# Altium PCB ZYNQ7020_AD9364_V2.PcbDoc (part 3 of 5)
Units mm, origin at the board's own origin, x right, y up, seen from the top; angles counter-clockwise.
Board outline 88.95 x 91.52 mm, 4 copper layers (Top Layer, Layer 1, Layer 2, Bottom Layer), stack 0.603 mm thick; 285 components, 278 nets, 1497 pads, 1247 vias.
Unrouted connection lines stored in the file: 367.
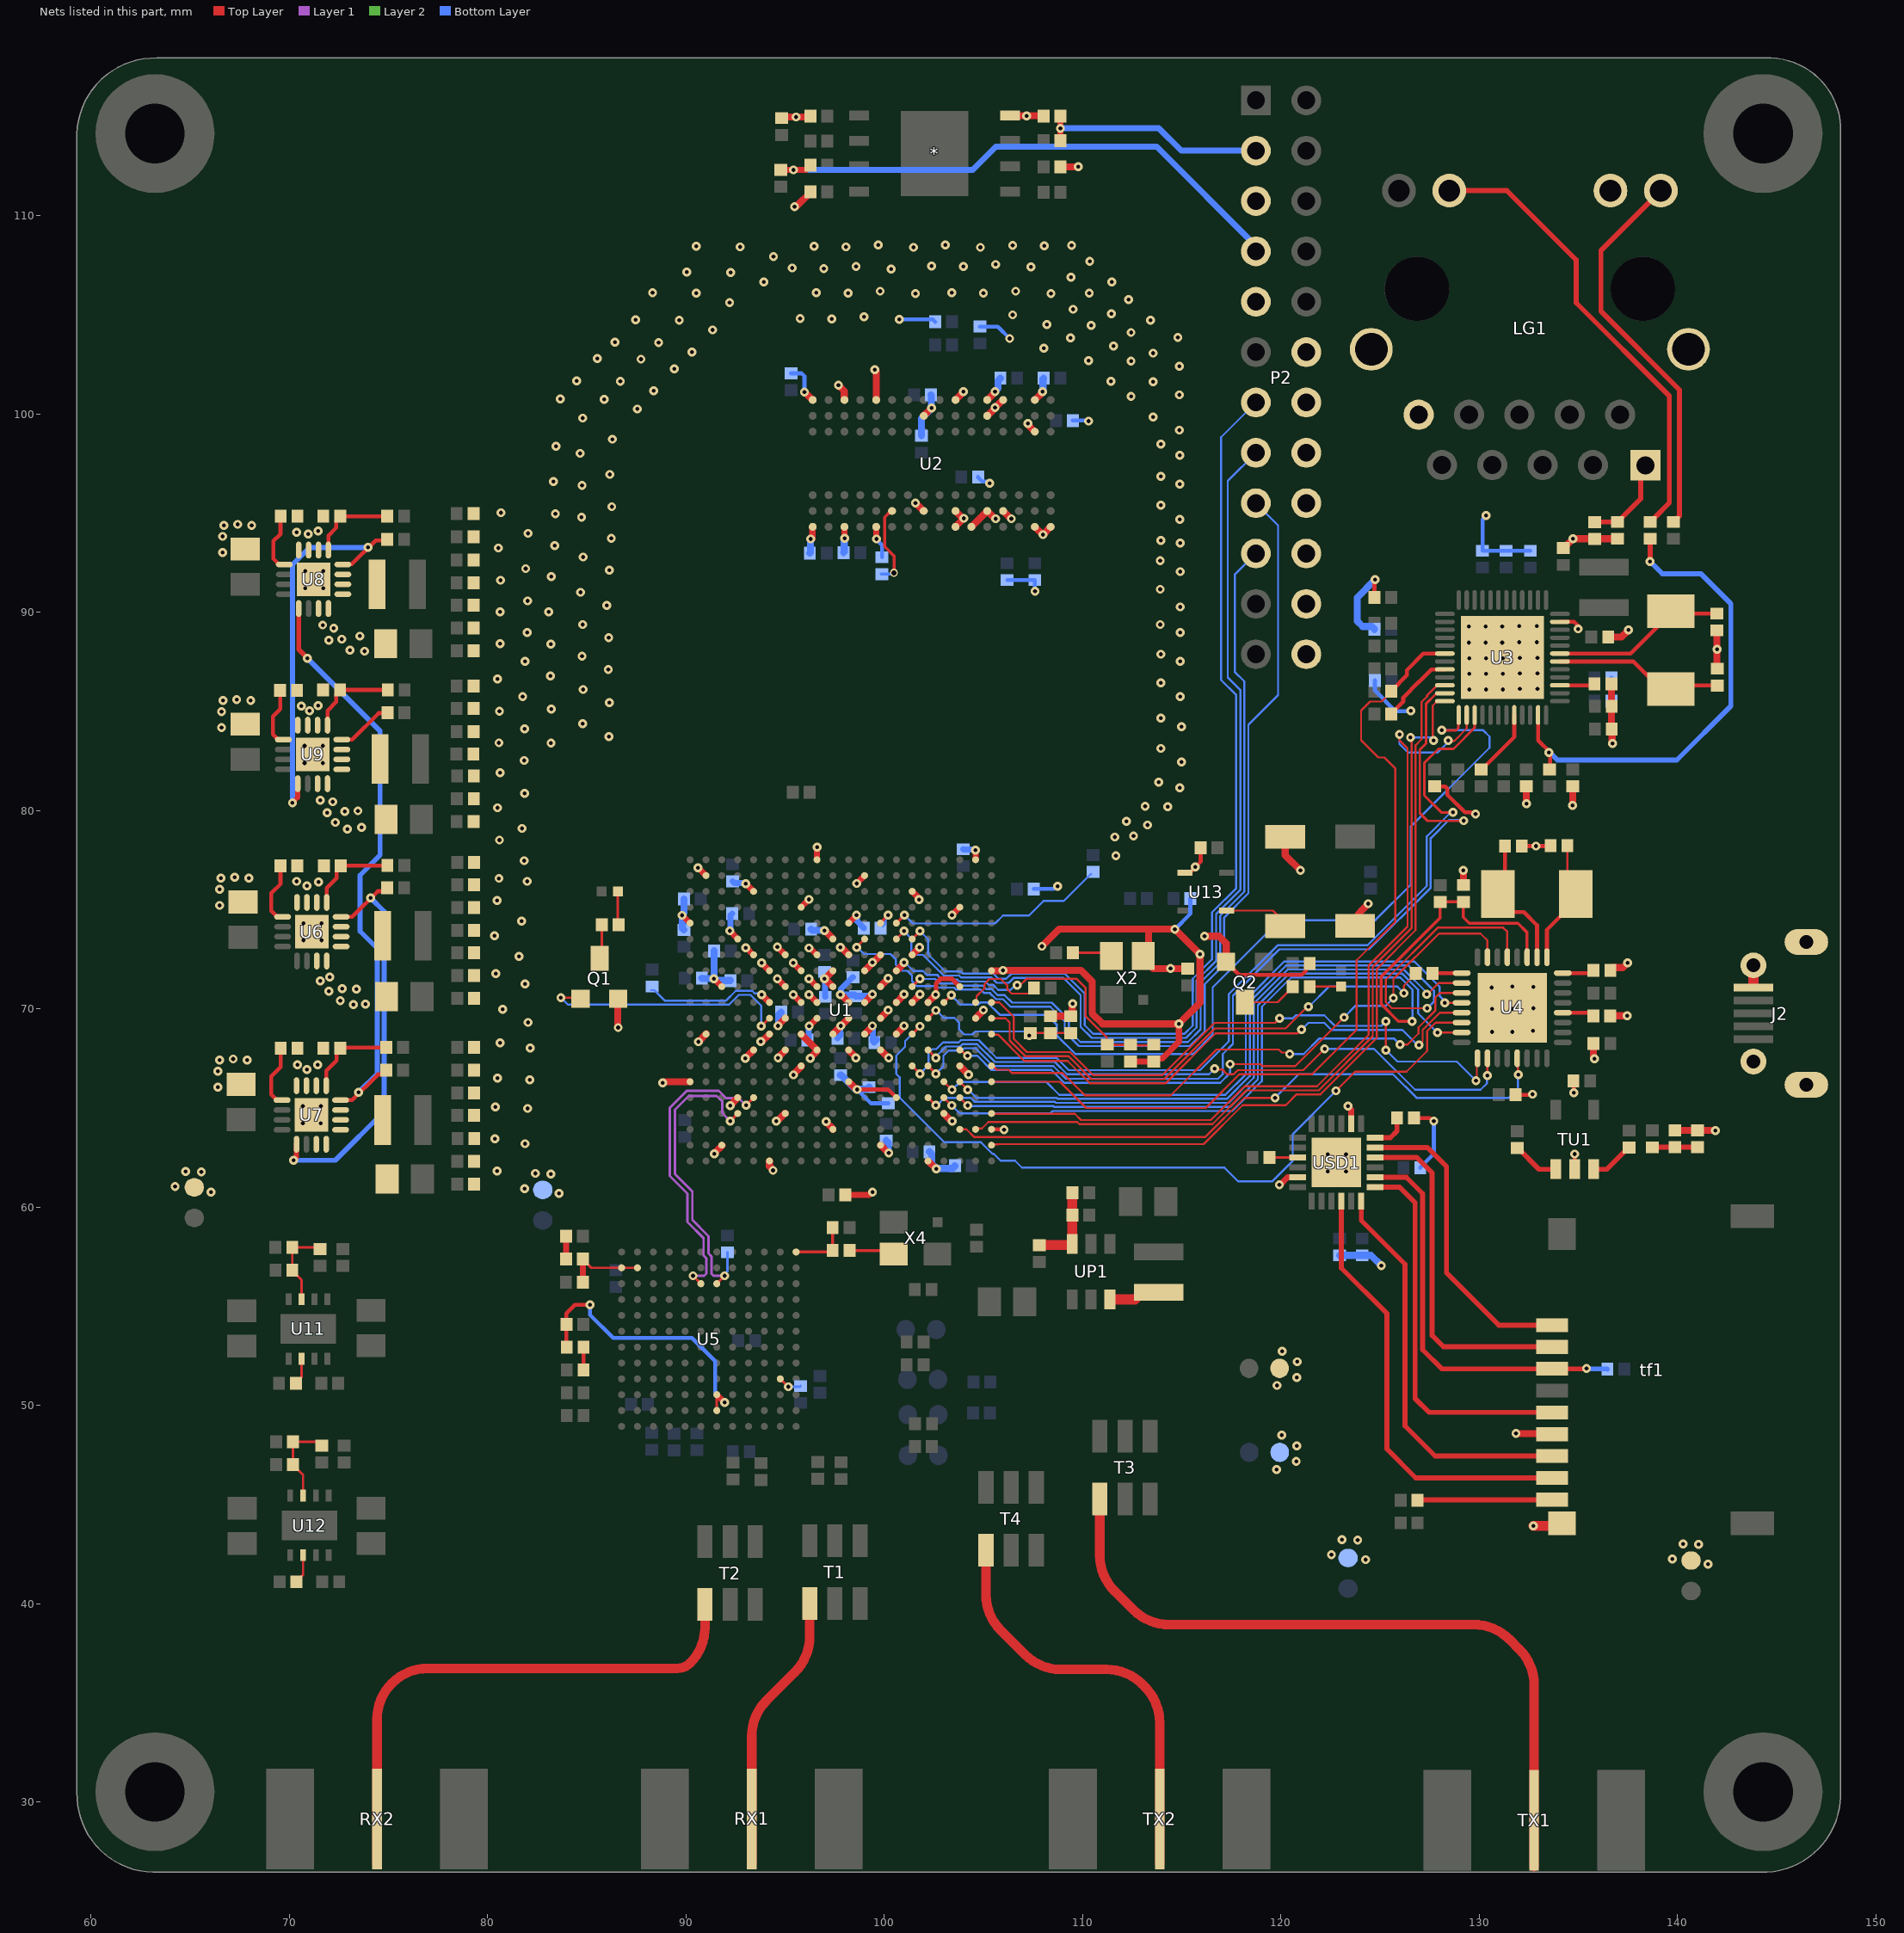
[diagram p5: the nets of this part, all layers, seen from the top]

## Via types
v1: diameter 0.45, hole 0.2, Top Layer to Bottom Layer, tented both sides, 995 vias
v2: diameter 0.406, hole 0.254, Top Layer to Bottom Layer, tented both sides, 118 vias
v3: diameter 1, hole 0.5, Top Layer to Bottom Layer, 116 vias
v4: diameter 0.5, hole 0.3, Top Layer to Bottom Layer, tented both sides, 16 vias
v5: diameter 0.406, hole 0.254, Top Layer to Bottom Layer, 2 vias

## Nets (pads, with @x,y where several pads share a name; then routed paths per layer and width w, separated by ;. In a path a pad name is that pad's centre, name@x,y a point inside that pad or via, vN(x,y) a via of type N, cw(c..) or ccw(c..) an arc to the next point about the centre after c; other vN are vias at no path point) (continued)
ETH_RXD3: R45.1 U1.A15 U3.18 | length 44
  Top Layer w0.102: U1.A15@105.41,66.32 108.858,66.32 110.18,64.999 116.214,64.999 117.916,66.7 121.575,66.7 123.825,68.95 123.825,72.446 125.781,74.402 125.781,82.118 125.222,82.677 124.917,82.677 124.054,83.541 124.054,85.042 124.509,85.497 125.082,85.497 125.572,85.987 R45.1@125.572,86.012
  Top Layer w0.203: R45.1@125.572,86.012 125.572,86.037 126.358,86.823 126.358,87.081 127.191,87.915 128.272,87.915 U3.18@128.276,87.918
ETH_TXCK: U1.A19 U3.22 | length 41.1
  Top Layer w0.102: U1.A19@105.41,63.12 105.456,63.167 105.737,63.167 105.74,63.17 116.11,63.17 118.073,65.133 120.251,65.133 120.802,65.684 121.996,65.684 124.841,68.529 124.841,72.009 126.797,73.965 126.797,83.29 127.102,83.595 127.102,85.472 127.375,85.745 127.375,85.807 127.886,86.318 U3.22@128.276,86.318
ETH_TXCTL: U1.F14 U3.27 | length 44.7
  Top Layer w0.127: U1.F14@101.41,67.12 v1@101.803,66.727 ; v1(128.676,79.908) 128.092,79.908 127.241,80.759 127.241,82.405 127.952,83.116 128.71,83.116 129.776,84.182 U3.27@129.776,84.818
  Bottom Layer w0.102: v1(101.807,66.727) 102.23,67.15 102.23,67.769 102.427,67.966 102.624,67.966 102.959,68.301 103.752,68.301 103.872,68.42 104.765,68.42 105.665,67.52 108.692,67.52 109.309,66.904 115.926,66.904 117.381,68.359 117.381,70.742 119.842,73.203 124.366,73.203 127.356,76.192 127.356,78.689 128.575,79.908 v1(128.676,79.908)
ETH_TXD0: U1.E14 U3.23 | length 46.8
  Top Layer w0.127: U1.E14@102.21,67.12 v1@102.603,66.727 ; U3.23@128.276,85.918 127.861,85.918 127.814,85.872 127.807,85.872 127.318,85.382 127.318,83.376 127.013,83.071 127.013,79.87 127.406,79.477 128.982,79.477 128.993,79.487 129.174,79.487 129.175,79.486 v1(129.227,79.486)
  Bottom Layer w0.102: v1(102.608,66.727) 102.985,67.104 102.985,67.628 103.251,67.894 103.92,67.894 104.04,68.014 104.596,68.014 105.496,67.114 108.524,67.114 109.166,66.472 116.84,66.472 117.072,66.704 117.072,67.72 117.585,68.233 117.585,70.658 119.926,73 124.451,73 127.559,76.108 127.559,78.605 128.485,79.531 129.182,79.531 v1(129.227,79.486)
ETH_TXD1: U1.B18 U3.24 | length 41.7
  Top Layer w0.102: U1.B18@104.61,63.92 104.657,63.968 104.928,63.968 105.247,64.287 109.742,64.287 109.844,64.186 116.551,64.186 118.253,65.888 121.912,65.888 124.638,68.613 124.638,72.109 126.594,74.065 v1@126.594,83.693 ; v1@127.573,83.501 127.587,83.501 127.66,83.575 127.66,85.293 127.886,85.518 U3.24@128.276,85.518
  Bottom Layer w0.102: v1(126.543,83.693) 127.559,83.693 v1(127.711,83.541)
ETH_TXD2: U1.D10 U3.25 | length 43.9
  Top Layer w0.127: U1.D10@103.01,70.32 103.012,70.32 103.375,70.684 v1(103.377,70.684) ; v1(128.118,84.049) 128.842,84.049 128.959,84.166 128.959,84.801 U3.25@128.976,84.818
  Top Layer w0.203: U3.25@128.976,84.428 U3.25@128.976,84.818
  Bottom Layer w0.102: v1(103.377,70.684) 103.848,70.213 104.743,70.213 104.847,70.317 105.207,70.317 105.824,69.699 108.204,69.699 108.694,69.209 108.694,68.667 109.645,67.716 115.586,67.716 116.569,68.699 116.569,71.079 119.963,74.473 124.773,74.473 126.543,76.243 126.543,79.179 130.531,83.166 130.531,83.733 130.215,84.049 v1(128.118,84.049)
ETH_TXD3: U1.A17 U3.26 | length 42.4
  Top Layer w0.102: U1.A17@105.41,64.72 105.428,64.703 109.614,64.703 109.928,64.389 116.467,64.389 118.169,66.091 121.828,66.091 124.435,68.698 124.435,72.193 126.39,74.149 126.39,83.134 125.984,83.541 v1(125.984,83.845) ; v1(128.448,83.541) 128.473,83.515 128.753,83.515 129.376,84.138 U3.26@129.376,84.818
  Top Layer w0.203: U3.26@129.372,84.815 U3.26@129.376,84.818
  Bottom Layer w0.102: v1(125.984,83.845) 125.984,83.363 126.416,82.931 127.914,82.931 128.448,83.464 v1(128.448,83.541)
FB_CLK_N: RX22.2 U1.U17 U5.G10 | length 16.1
  Top Layer w0.127: U5.G10@91.554,56.134 v1(91.954,56.534) ; v1(92.23,64.329) 92.23,64.335 92.623,64.728 U1.U17@92.623,64.729
  Layer 1 w0.127: v1(91.954,56.534) 91.391,56.534 91.281,56.644 91.281,57.518 91.142,57.658 91.142,58.533 90.324,59.35 90.324,60.232 90.324,60.782 89.44,61.666 89.44,64.904 90.145,65.608 91.549,65.608 91.827,65.33 91.827,64.733 v1(92.23,64.329)
  Bottom Layer w0.127: v1(91.954,56.534) 91.954,56.622 92.1,56.768 RX22.2@92.1,57.716
FB_CLK_P: U1.T16 U5.F10 | length 15.5
  Top Layer w0.127: v1(90.357,56.533) U5.F10@90.754,56.134 U5.F10@90.754,56.134 ; v1@93.03,65.135 U1.T16@93.423,65.529
  Layer 1 w0.127: v1(90.357,56.533) 90.917,56.533 91.027,56.644 91.027,57.413 90.888,57.553 90.888,58.428 90.07,59.245 90.07,60.677 89.186,61.561 89.186,65.009 90.039,65.862 91.654,65.862 92.017,65.499 92.661,65.499 v1(93.03,65.13)
FPGA_DONE: Q1.1 U1.R11 | length 13.3
  Top Layer w0.102: v1(83.693,70.561) 84.633,70.561 Q1.1@84.684,70.51
  Top Layer w0.127: v1@93.802,69.123 U1.R11@94.2,69.52
  Bottom Layer w0.102: v1(83.693,70.561) 84.043,70.211 92.182,70.211 92.671,70.701 93.257,70.701 93.797,70.161 v1(93.797,69.123)
FPGA_TCK: P2.10 U1.F9 | length 42.2
  Top Layer w0.127: U1.F9@101.41,71.12 101.803,71.514 v1(101.803,71.523)
  Bottom Layer w0.102: v1(101.803,71.523) 101.825,71.501 102.574,71.501 102.803,71.272 103.608,71.272 103.71,71.171 104.958,71.171 105.132,70.997 105.414,70.997 105.725,70.686 106.073,70.686 106.449,70.309 108.456,70.309 109.304,69.461 109.304,68.92 109.898,68.326 115.316,68.326 115.959,68.969 115.959,71.34 116.942,72.323 116.942,74.693 118.161,75.913 118.161,86.512 117.678,86.995 117.678,91.897 P2.10@118.745,92.964
FPGA_TDI: P2.8 U1.G6 | length 50.1
  Top Layer w0.127: U1.G6@100.61,73.52 v1@101.003,73.914
  Layer 2 w0.102: v1@101.092,73.838 v1@101.092,73.863
  Bottom Layer w0.102: v1(101.003,73.918) 101.371,73.55 101.371,72.78 101.431,72.72 101.956,72.72 102.997,71.679 103.777,71.679 103.819,71.637 103.878,71.577 105.408,71.577 105.675,71.311 106.287,71.311 106.541,71.565 109.03,71.565 109.906,70.689 109.906,69.088 110.465,68.529 115.222,68.529 115.756,69.063 115.756,71.429 116.738,72.411 116.738,74.778 117.958,75.997 117.958,86.081 117.323,86.716 117.323,96.622 P2.8@118.745,98.044
FPGA_TDO: P2.7 U1.F6 | length 51.6
  Top Layer w0.127: U1.F6@101.41,73.52 v1@101.803,73.914
  Layer 2 w0.102: v1@101.854,73.863 v1@101.854,73.889
  Bottom Layer w0.102: v1(101.803,73.918) 102.21,73.511 102.21,72.754 103.081,71.882 103.861,71.882 103.963,71.78 105.493,71.78 105.759,71.514 106.151,71.514 106.405,71.768 109.114,71.768 110.109,70.773 110.109,69.172 110.549,68.732 115.138,68.732 115.553,69.147 115.553,71.513 116.535,72.496 116.535,74.862 117.754,76.081 117.754,85.827 116.992,86.589 116.992,98.831 P2.7@118.745,100.584
FPGA_TMS: P2.9 U1.J6 | length 49.8
  Top Layer w0.127: v1(98.616,73.105) 98.616,73.127 U1.J6@99.01,73.52
  Bottom Layer w0.102: v1(98.616,73.105) 98.634,73.105 98.977,72.762 100.314,72.762 100.58,72.495 100.58,72.228 100.892,71.916 101.159,71.916 101.403,71.673 101.403,71.389 101.647,71.145 102.642,71.145 102.718,71.069 103.524,71.069 103.626,70.968 104.874,70.968 105.048,70.793 105.33,70.793 105.641,70.482 105.989,70.482 106.365,70.106 108.372,70.106 109.101,69.377 109.101,68.836 109.814,68.123 115.418,68.123 116.162,68.867 116.162,71.247 117.145,72.23 117.145,74.609 118.364,75.828 118.364,84.328 119.863,85.827 119.863,94.386 P2.9@118.745,95.504
GND: *.4 C1.2 C2.1 C3.1 C4.1 C5.1 C6.1 C7.1 C8.1 C9.1 C10.1 C11.1 C12.1 C13.1 C33.1 C34.1 C35.1 C36.1 C37.1 C38.1 C39.1 C49.1 C50.1 C51.1 C52.1 C53.1 C57.1 C61.1 C62.1 C67.1 C68.1 C69.1 C70.1 C71.1 C72.1 C73.1 C74.1 C75.1 C76.1 C77.1 C78.1 C80.1 C81.2 C82.1 C83.1 C85.1 C86.1 C87.1 C89.1 C90.1 C91.1 C96.1 C98.2 C99.2 C100.2 C101.2 C102.2 C103.2 C104.2 C105.2 C106.2 C107.2 C108.2 C109.1 C110.1 C111.2 C112.2 C113.1 C114.1 C115.1 C116.1 C117.2 C118.2 C119.1 C120.2 C121.1 C122.2 C123.2 C124.2 C125.2 C126.2 C127.1 C128.1 C129.2 C130.1 C131.1 C132.2 C133.2 C134.2 C135.2 C136.2 C137.2 C138.2 C139.2 C141.2 C148.2 C149.2 C159.1 C160.1 C161.1 C181.2 C182.2 C183.2 C187.1 C188.1 C189.1 C190.1 C191.1 C192.1 C193.1 J2.5 J2.6 J2.7 J2.8 J2.9 LG1.12 LG1.P10 LG1.SHIELD0 LG1.SHIELD1 P2.3 P2.5 P2.18 P2.19 P2.20 P2.21 P2.22 P2.23 P2.24 Q1.2 Q2.2 R1.2 R2.1 R5.1 R6.2 R11.2 R12.2 R17.2 R18.2 R26.2 R28.2 R36.1 R40.1 R44.2 R49.1 R51.1 R53.1 R54.2 R56.1 R62.1 R65.2 R69.2 RESET.1 RX6.2 RX7.2 RX8.2 RX13.2 RX14.2 RX15.2 tf1.6 tf1.10 TU1.2 U1.A8 U1.A18 U1.B1 U1.B11 U1.C4 U1.C9 U1.C14 U1.D17 U1.E10 U1.E20 U1.F3 U1.F7 U1.F10 U1.G10 U1.G12 U1.G16 U1.H7 U1.H9 U1.H11 U1.H13 U1.H19 U1.J2 U1.J8 U1.J10 U1.J12 U1.K5 U1.K7 U1.K10 U1.K11 U1.K13 U1.K15 U1.L8 U1.L9 U1.L12 U1.L18 U1.M1 U1.M7 U1.M9 U1.M10 U1.M11 U1.M13 U1.N4 U1.N8 U1.N10 U1.N12 U1.N14 U1.P7 U1.P9 U1.P11 U1.P13 U1.P17 U1.R8 U1.R12 U1.R20 U1.T3 U1.T7 U1.T13 U1.U6 U1.U16 U1.V9 U1.V19 U1.W2 U1.W12 U1.Y5 U1.Y15 U2.A9 U2.B1 U2.B3 U2.B9 U2.D1 U2.D8 U2.E1 U2.E2 U2.E8 U2.F9 U2.G1 U2.G8 U2.G9 U2.J2 U2.J8 U2.M1 U2.M9 U2.P1 U2.P9 U2.T1 U2.T9 U3.0 U3.47 U4.0 U6.6 U6.7 U6.8 U6.15 U6.16 U6.20 U7.6 U7.7 U7.8 U7.15 U7.16 U7.20 U8.6 U8.7 U8.8 U8.15 U8.16 U8.20 U9.6 U9.7 U9.8 U9.15 U9.16 U9.20 U13.1 USD1.2 USD1.11 USD1.25 USR_BTN.1 X2.2 | length 198.2
  Top Layer w0.2: U1.A18@105.41,63.92 v1@106.006,63.92 ; Q2.2@117.246,72.365 117.905,71.706 121.058,71.706 121.256,71.904 121.256,72.088 R65.2@121.456,72.288 ; R36.1@124.721,90.754 v1@124.721,91.574 ; R62.1@126.714,64.491 127.533,64.491 v1@127.711,64.313 ; C125.2@127.763,81.218 128.287,81.218 128.405,81.101 128.405,80.79 129.286,79.908 129.577,79.908 129.606,79.88 129.816,79.88 v1@129.819,79.883 ; C141.2@131.845,65.659 v1@132.664,65.659 ; R69.2@134.754,66.37 134.777,66.347 v1(134.777,65.773) ; TU1.2@134.823,61.905 v1@134.823,62.662
  Top Layer w0.203: v1@98.605,65.929 v1(98.63,65.929) 100.201,65.929 U1.G16@100.61,65.52 ; U13.1@115.174,76.86 115.402,76.86 115.958,77.416 C132.2@115.958,78.13 ; C122.2@132.156,78.207 133.579,78.207 C123.2@133.604,78.232 ; U3.47@134.076,89.518 134.789,89.518 v1@135.052,89.256
  Top Layer w0.229: v1(102.594,70.713) 102.619,70.738 102.619,71.282 102.848,71.511 103.419,71.511 U1.C9@103.81,71.12
  Top Layer w0.305: v1@89.817,74.714 U1.Y5@90.21,74.32 ; v1@90.617,77.114 U1.W2@91.01,76.72 ; v1@91.417,71.513 U1.V9@91.81,71.12 ; v1(92.21,73.936) 92.21,73.928 92.61,73.528 U1.U6@92.61,73.52 ; v1(93.01,73.079) 93.039,73.079 93.398,72.72 U1.T7@93.41,72.72 ; v1@93.017,76.314 U1.T3@93.41,75.92 ; v1@93.817,72.314 U1.R8@94.21,71.92 ; v1@94.617,71.513 U1.P9@95.01,71.12 ; v1@94.617,73.114 U1.P7@95.01,72.72 ; v1@95.417,70.714 U1.N10@95.81,70.32 ; v1@95.417,72.314 U1.N8@95.81,71.92 ; U1.N4@95.81,75.12 v1@96.203,75.513 ; v1(96.21,73.067) 96.238,73.039 96.279,73.039 96.598,72.72 U1.M7@96.61,72.72 ; v1@96.217,69.127 U1.M11@96.61,69.52 ; v1@96.217,70.714 U1.M10@96.61,70.32 ; v1@96.217,71.513 U1.M9@96.61,71.12 ; v1@96.377,93.7 U2.T9@96.377,94.3 ; U1.M1@96.596,77.546 v1@96.596,78.206 ; U2.P9@97.994,94.31 97.995,94.309 97.995,93.727 v1(97.997,93.726) ; C71.1@98.037,60.604 99.254,60.604 v1(99.406,60.757) ; U1.K5@98.21,74.32 98.21,74.327 98.603,74.72 v1(98.603,74.727) ; v1(98.606,76.321) 98.608,76.321 99.008,76.72 U1.J2@99.01,76.72 ; U2.M9@99.595,94.309 99.601,94.303 99.601,93.708 v1(99.608,93.701) ; U1.F3@101.41,75.92 v1@101.803,75.527 ; v1@103.417,74.727 U1.C4@103.81,75.12 ; v1(104.597,78.003) 104.604,77.997 104.604,77.527 U1.B1@104.61,77.52 ; C149.2@112.42,67.342 C148.2@113.589,67.342 113.736,67.49 114.023,67.49 114.862,68.329 v1(114.862,69.24) ; v1(119.93,61.121) 119.969,61.121 120.344,61.496 120.853,61.496 USD1.11@120.856,61.498 ; v1@123.444,65.024 123.556,64.912 USD1.2@123.556,64.198
  Top Layer w0.356: v1@86.563,69.063 86.563,70.485 Q1.2@86.589,70.51 ; v1(88.824,66.269) 88.849,66.269 88.9,66.319 90.209,66.319 U1.Y15@90.21,66.32 ; v1@90.63,68.341 U1.W12@91.01,68.72 U1.W12@91.023,68.734 ; v1@91.43,62.715 U1.V19@91.823,63.109 ; v1(92.237,65.109) 92.237,65.135 92.61,65.508 U1.U16@92.61,65.52 ; v1@92.991,67.502 U1.T13@93.41,67.92 ; v1@93.817,68.327 U1.R12@94.21,68.72 ; U1.R20@94.21,62.32 94.21,62.057 94.394,61.873 v1(94.394,61.848) ; v1(94.562,64.329) 94.588,64.329 94.979,64.72 U1.P17@95.01,64.72 ; v1@94.616,69.127 U1.P11@95.01,69.52 ; v1(94.65,67.521) 94.65,67.546 95.01,67.906 U1.P13@95.01,67.92 ; R53.1@94.818,114.928 94.872,114.982 96.219,114.982 R49.1@96.273,115.037 ; v1(95.417,66.666) 95.417,66.691 95.81,67.085 U1.N14@95.81,67.12 ; v1(95.479,110.465) 95.497,110.483 95.586,110.483 96.28,111.176 C133.2@96.28,111.201 ; U1.N12@95.81,68.72 U1.M13@96.61,67.92 96.61,67.862 96.275,67.527 v1(96.275,67.502) ; v1@96.001,101.104 U2.T1@96.394,100.711 ; v1(96.991,71.514) 97.003,71.514 U1.L8@97.41,71.92 ; v1@97.016,71.514 U1.L9@97.41,71.12 ; v1(97.073,64.314) 97.073,64.288 97.41,63.951 U1.L18@97.41,63.92 ; U1.L12@97.41,68.72 U1.K11@98.21,69.52 ; v1(97.688,101.448) 97.985,101.151 97.985,100.719 U2.P1@97.994,100.711 ; v1(97.791,73.105) 97.817,73.105 98.201,72.72 U1.K7@98.21,72.72 ; v1@97.817,70.714 U1.K10@98.21,70.32 ; U1.K15@98.21,66.32 98.214,66.32 v1@98.605,65.929 ; U1.K13@98.21,67.92 98.21,67.911 98.568,67.553 v1(98.568,67.527) ; U1.J12@99.01,68.72 v1@99.403,69.114 ; U1.J10@99.01,70.32 v1@99.403,70.714 ; U1.J8@99.01,71.92 U1.H7@99.81,72.72 ; v1(99.517,102.235) 99.594,102.158 U2.M1@99.594,100.711 ; U1.H19@99.81,63.12 v1@100.203,62.727 ; U1.H13@99.81,67.92 v1@100.203,67.527 ; U1.H11@99.81,69.52 v1@100.203,69.914 ; U1.H9@99.81,71.12 99.81,71.127 100.2,71.517 v1(100.2,71.542) ; U1.G12@100.61,68.72 v1@101.003,69.114 ; U1.G10@100.61,70.32 v1@101.003,70.714 ; U1.F10@101.41,70.32 v1@101.803,70.714 ; U1.F7@101.41,72.72 v1@101.803,73.114 ; v1@101.601,95.504 U2.J8@101.994,95.111 ; U2.J2@101.994,99.911 v1(102.386,100.306) v1(102.386,100.306) ; U1.E20@102.21,62.32 v1@102.603,61.927 ; U1.E10@102.21,70.32 102.594,70.704 v1(102.594,70.713) ; U1.D17@103.01,64.72 v1@103.403,64.327 ; U2.G9@103.594,94.31 103.594,94.316 104.013,94.736 v1(104.013,94.742) ; U2.G8@103.594,95.111 v1@103.987,94.717 ; U2.G1@103.594,100.711 v1@103.987,101.104 ; U1.C14@103.81,67.12 104.251,66.679 v1(104.256,66.679) ; U2.F9@104.394,94.31 U2.E8@105.194,95.111 v1@105.587,94.717 ; U1.B11@104.61,69.52 v1@105.003,69.914 ; U2.E2@105.194,99.911 v1@105.587,100.304 ; U2.E1@105.194,100.711 v1@105.587,101.104 ; U1.A8@105.41,71.92 105.974,71.92 v1(105.992,71.938) ; v1(105.587,100.329) 105.6,100.329 105.982,100.711 U2.D1@105.994,100.711 ; U2.D8@105.994,95.111 v1@106.387,94.717 ; v1@106.049,71.92 106.065,71.936 109.928,71.936 110.49,71.374 110.49,69.755 111.004,69.24 v1(114.862,69.24) 115.929,70.307 115.929,72.642 115.947,72.66 115.947,72.727 v1(115.929,72.745) v1(114.658,74.016) 113.226,74.016 ; *.4@106.34,115.052 106.347,115.044 108.026,115.044 R54.2@108.033,115.037 ; v1@107.201,99.504 U2.B3@107.594,99.111 ; U2.B9@107.594,94.31 v1@107.987,93.917 ; U2.B1@107.594,100.711 v1@107.987,101.104 ; v1(107.95,73.152) 108.814,74.016 113.226,74.016 ; v1(108.013,93.917) 108.013,93.923 108.394,94.304 U2.A9@108.394,94.31 ; C119.1@108.389,69.625 R28.2@109.405,69.625 109.482,69.701 109.482,70.238 v1(109.5,70.256) ; R51.1@108.883,112.471 v1(109.779,112.471) ; C120.2@115.316,72.028 v1(114.439,72.028) 113.563,72.028 113.055,72.535 X2.2@113.055,72.66 113.335,72.939 113.335,73.907 113.226,74.016 ; v1(116.154,73.66) 116.891,73.66 117.246,73.304 Q2.2@117.246,72.365 ; RESET.1@120.22,78.673 120.22,77.748 v1@120.98,76.987 ; USR_BTN.1@123.747,74.184 cw(c124.81,74.184) 124.059,74.935 v1@124.384,75.26 ; C121.1@129.21,76.244 v1(129.21,76.987) ; v1(131.861,48.585) 131.879,48.567 133.658,48.567 tf1.6@133.685,48.541 ; v1(132.386,80.341) R40.1@132.386,81.218 ; C126.2@134.239,93.237 134.264,93.237 v1(134.735,93.707) C111.2@136.982,93.707 ; v1@134.722,80.263 C127.1@134.722,81.218 ; v1@135.77,67.557 C137.2@135.77,68.25 ; C114.1@136.511,88.748 137.185,88.748 v1@137.541,89.103 ; C129.2@136.613,69.647 v1(137.465,69.647) ; R44.2@136.62,71.933 136.62,71.958 136.742,72.08 137.256,72.08 v1(137.49,72.314) ; R26.2@136.671,86.393 136.681,86.384 136.681,84.116 C115.1@136.69,84.107 136.71,84.087 136.71,83.406 v1(136.728,83.388) ; C135.2@139.878,63.867 C136.2@141.021,63.867 v1@141.898,63.867 ; C117.2@141.987,89.085 141.999,89.073 141.999,87.168 C118.2@142.012,87.155
  Top Layer w0.5: v1@132.74,43.917 134.061,43.917 tf1.10@134.185,44.041
  Top Layer w0.508: 143.837,71.303 J2.6@143.837,72.192
  Bottom Layer w0.2: R1.2@95.301,102.05 95.841,102.05 95.975,101.916 v1(95.975,101.104) ; v1(99.608,93.701) 99.608,93.658 99.89,93.376 R6.2@99.89,92.776 ; v1(100.762,104.775) 102.445,104.775 R5.1@102.572,104.648 ; C100.2@104.736,96.825 104.736,96.8 104.936,96.6 105.203,96.6 v1@105.308,96.495 ; C99.2@104.826,104.413 105.722,104.413 v1(106.324,103.81) ; C159.1@106.197,91.625 C98.2@107.594,91.625 v1@107.594,91.059 ; C101.2@109.511,99.67 110.16,99.67 v1@110.185,99.644 ; v1(114.658,74.016) 115.436,74.794 R56.1@115.436,75.565 ; C109.1@124.747,86.571 124.747,86.048 125.781,85.014 v1@126.594,85.014 ; C139.2@127.037,61.976 127.037,62.001 127.718,62.682 v1(127.718,64.327) ; v1@130.353,94.869 130.175,94.691 C130.1@130.175,93.103 C113.1@131.369,93.103 C124.2@132.588,93.103 ; C131.1@136.671,86.698 136.728,86.641 v1(136.728,83.388)
  Bottom Layer w0.203: v1(98.63,65.929) 99.325,65.234 C68.1@100.203,65.234 ; C105.2@107.537,76.048 108.544,76.048 108.671,76.175 v1(108.737,76.175)
  Bottom Layer w0.305: v1(92.21,73.936) 92.238,73.964 92.238,74.705 C81.2@92.336,74.803 ; C104.2@92.354,76.435 92.448,76.341 92.982,76.341 v1(93.01,76.314) ; C35.1@96.132,68.428 96.189,68.484 96.189,69.093 v1(96.217,69.121) ; v1(96.991,71.514) 97.009,71.495 97.009,70.624 C34.1@97.028,70.605 ; C33.1@97.644,68.504 97.775,68.635 97.775,69.111 v1(97.803,69.139) ; v1(97.791,70.714) 97.819,70.741 97.819,71.003 98.4,71.584 C70.1@98.425,71.584 ; v1@98.603,74.688 v1(98.603,74.727) 98.631,74.699 98.631,74.426 98.965,74.091 R2.1@98.965,74.066 R2.1@98.818,74.214 ; v1@99.367,69.064 99.403,69.1 v1(99.403,69.139) 99.431,69.111 99.431,68.368 C38.1@99.499,68.301 C38.1@99.646,68.448 ; C106.2@103.988,78.047 104.01,78.025 104.575,78.025 v1(104.597,78.003)
  Bottom Layer w0.356: C83.1@89.891,73.983 89.828,74.046 89.828,74.696 v1(89.81,74.714) 89.81,74.739 89.897,74.826 C107.2@89.897,75.54 ; C82.1@90.798,71.552 90.818,71.532 91.392,71.532 v1(91.41,71.513) ; C73.1@91.421,72.923 91.416,72.918 91.416,71.519 v1(91.41,71.513) ; C72.1@92.241,71.425 91.524,71.425 91.436,71.513 v1(91.41,71.513) ; v1(94.64,69.139) 94.64,69.164 94.677,69.201 94.677,69.702 C96.1@94.8,69.825 ; C161.1@96.247,92.989 96.273,93.015 96.273,93.683 v1(96.291,93.701) ; C39.1@97.79,66.656 97.815,66.656 98.524,65.947 98.612,65.947 v1(98.63,65.929) 98.649,65.947 99.138,65.947 C36.1@99.238,66.047 ; v1(97.791,70.714) 97.809,70.696 98.487,70.696 C69.1@98.552,70.631 99.269,70.631 99.377,70.739 v1(99.403,70.739) ; C160.1@97.949,93.015 97.979,93.044 97.979,93.708 v1(97.997,93.726) ; C80.1@100.101,63.354 100.211,63.245 100.211,62.745 v1(100.229,62.727) ; C1.2@101.879,98.901 101.879,99.773 102.386,100.28 v1(102.386,100.306) 102.371,100.321 102.371,100.949 C103.2@102.355,100.965 ; C90.1@102.279,62.789 102.401,62.667 102.401,62.18 102.629,61.953 v1(102.629,61.927) 102.647,61.945 103.44,61.945 103.563,62.067 C85.1@103.563,62.078 ; v1(105.587,101.13) 105.587,101.155 105.733,101.301 105.733,101.681 C102.2@105.855,101.803 ; v1(107.987,101.13) 108.005,101.148 108.005,101.775 C108.2@108.033,101.803 ; C138.2@122.961,57.563 C134.2@124.104,57.563 124.555,57.563 v1(125.07,57.048) ; C110.1@124.722,89.136 124.722,89.161 124.599,89.283 124.127,89.283 123.85,89.56 123.85,90.737 v1(124.754,91.641)
  other v1: 141.554,41.986 124.282,42.215 139.751,42.24 122.555,42.469 141.072,42.977 140.284,43.002 123.876,43.205 123.088,43.231 132.74,43.924 119.786,46.761 120.777,47.168 120.802,47.955 120.04,48.489 119.812,51.003 120.802,51.41 120.828,52.197 120.066,52.73 83.591,60.681 66.04,60.757 81.864,60.935 64.237,61.036 83.185,61.671 82.398,61.697 65.557,61.773 64.77,61.798 122.377,61.798 123.292,61.798 80.467,61.824 122.377,62.662 123.292,62.662 91.43,62.69 134.83,62.676 81.89,63.195 80.366,63.449 141.912,63.857 106.041,63.905 70.677,64.222 71.577,64.218 103.429,64.327 82.017,64.973 80.391,65.049 70.677,65.085 71.592,65.085 123.393,65.1 132.702,65.688 66.4,66.045 82.118,66.421 80.493,66.497 66.4,66.858 70.891,66.929 70.409,67.183 71.425,67.183 66.476,67.417 67.873,67.417 67.162,67.468 135.813,67.483 92.991,67.502 100.229,67.527 82.144,68.021 80.62,68.275 90.63,68.336 93.777,68.351 130.658,68.834 131.674,68.834 132.715,68.885 86.581,69.052 101.003,69.139 82.042,69.314 100.203,69.939 105.003,69.939 80.758,69.981 130.658,70.002 131.674,70.002 132.74,70.028 73.228,70.206 73.838,70.231 72.568,70.409 95.41,70.714 96.21,70.714 101.003,70.739 101.803,70.739 71.984,70.891 73.381,70.993 72.669,71.018 130.632,71.069 132.74,71.095 131.674,71.12 81.89,71.247 71.552,71.399 94.61,71.513 96.21,71.513 72.034,71.603 80.405,71.776 93.81,72.314 95.41,72.314 99.403,72.339 81.585,72.644 94.61,73.114 101.778,73.101 70.714,73.457 71.628,73.457 80.34,73.685 70.714,74.32 71.628,74.32 81.712,74.422 103.417,74.72 66.476,75.215 124.405,75.299 80.467,75.463 96.203,75.52 101.752,75.514 66.476,76.028 70.891,76.2 71.476,76.403 70.358,76.429 81.991,76.429 66.552,76.586 67.949,76.586 80.569,76.578 67.238,76.637 120.992,76.978 90.61,77.114 115.687,77.152 81.839,77.47 111.684,77.724 96.622,78.156 132.867,78.207 80.594,78.511 111.633,78.664 112.573,78.715 72.923,79.07 81.737,79.096 73.635,79.146 113.284,79.273 72.314,79.4 112.217,79.451 129.819,79.832 71.907,79.883 72.796,79.959 73.457,79.985 80.493,80.137 114.3,80.188 113.157,80.213 134.714,80.258 72.187,80.442 71.552,80.518 81.864,80.874 114.91,81.153 113.843,81.432 80.62,81.915 70.764,82.398 71.679,82.398 114.986,82.448 81.839,82.525 113.944,83.134 70.764,83.261 71.679,83.261 83.194,83.398 80.569,83.414 86.115,83.728 81.864,84.125 66.577,84.181 114.986,84.226 84.795,84.388 113.944,84.658 66.577,84.994 80.594,85.014 71.018,85.039 126.556,85.039 83.21,85.115 70.606,85.268 71.45,85.293 86.131,85.446 66.654,85.553 68.051,85.553 67.339,85.603 81.763,85.75 114.935,85.75 84.811,86.106 129.515,86.106 130.353,86.106 131.191,86.106 132.055,86.131 132.944,86.131 113.944,86.436 80.493,86.639 83.16,86.792 129.515,86.893 130.353,86.893 131.191,86.893 132.055,86.919 132.944,86.919 86.081,87.122 81.89,87.528 114.935,87.528 129.515,87.681 130.353,87.681 131.191,87.681 132.055,87.706 132.944,87.706 84.76,87.782 113.944,87.884 73.787,88.036 73.05,88.087 141.999,88.127 83.185,88.392 80.62,88.417 129.489,88.468 130.327,88.468 131.166,88.468 132.029,88.494 132.918,88.494 71.984,88.595 72.644,88.646 86.106,88.722 73.558,88.798 81.991,88.976 114.935,88.976 137.541,89.11 135,89.162 72.238,89.205 129.489,89.281 130.327,89.281 131.166,89.281 132.029,89.306 132.918,89.306 71.679,89.357 84.785,89.383 113.919,89.383 80.62,90.018 83.083,90.018 114.935,90.272 86.004,90.348 82.017,90.576 84.684,91.008 107.603,91.056 113.919,91.161 70.79,91.211 71.704,91.211 80.645,91.618 83.21,91.796 114.935,92.05 70.79,92.075 71.704,92.075 86.131,92.126 81.915,92.202 113.919,92.608 84.811,92.786 66.624,93.015 80.543,93.243 83.388,93.37 114.935,93.497 113.944,93.624 86.233,93.726 66.624,93.828 70.942,93.955 82.042,93.98 70.358,94.031 71.45,94.107 66.7,94.386 68.097,94.386 67.386,94.437 114.91,94.691 105.613,94.717 106.413,94.717 84.734,94.793 130.349,94.881 83.414,94.971 80.67,95.021 86.258,95.326 113.944,95.402 101.575,95.504 84.76,96.393 114.91,96.469 105.317,96.507 83.312,96.596 113.944,96.85 86.157,96.952 114.91,97.917 84.658,98.019 83.439,98.374 113.944,98.476 86.284,98.73 114.884,99.187 107.239,99.517 110.312,99.644 84.785,99.797 113.563,99.847 87.554,100.254 85.877,100.736 83.668,100.762 112.446,100.889 114.884,100.965 103.987,101.13 88.367,101.168 113.563,101.625 86.69,101.651 111.43,101.651 84.48,101.676 89.408,102.286 114.884,102.413 112.446,102.667 110.312,102.692 87.732,102.768 85.522,102.794 113.563,103.073 90.297,103.124 108.052,103.327 111.557,103.429 88.621,103.607 86.411,103.632 109.398,103.838 114.808,103.861 112.446,104.115 91.338,104.242 110.439,104.47 108.204,104.521 89.662,104.724 113.436,104.724 87.452,104.75 97.358,104.8 95.758,104.826 98.984,104.902 106.477,105.004 111.455,105.054 109.525,105.283 92.202,105.613 112.319,105.766 101.575,106.07 108.407,106.07 90.526,106.096 98.171,106.096 105.004,106.096 110.338,106.096 88.316,106.121 96.571,106.121 103.403,106.121 99.797,106.197 106.629,106.197 93.929,106.655 111.481,106.655 109.423,106.909 92.253,107.137 90.043,107.163 100.355,107.315 96.952,107.34 95.352,107.366 107.391,107.417 98.577,107.442 103.988,107.442 102.387,107.467 105.613,107.544 110.363,107.696 94.412,107.95 101.473,108.407 104.851,108.407 92.735,108.433 98.069,108.433 90.526,108.458 96.469,108.458 108.077,108.483 106.477,108.509 109.449,108.509 99.695,108.534 103.073,108.534 95.545,114.982 107.186,115.044
NetC6_2: C6.2 U6.9 | length 3.2
  Top Layer w0.203: C6.2@69.552,77.216 69.552,76.298 69.088,75.834 69.088,74.942 69.392,74.638 U6.9@69.657,74.638
NetC7_2: C7.2 U7.9 | length 3.2
  Top Layer w0.203: C7.2@69.559,68.021 69.559,67.07 69.088,66.599 69.088,65.673 69.367,65.395 U7.9@69.632,65.395
NetC11_2: C11.2 U8.9 | length 3
  Top Layer w0.203: C11.2@69.552,94.869 69.552,93.954 69.19,93.592 69.19,92.702 69.478,92.413 U8.9@69.743,92.413
NetC13_2: C13.2 U9.9 | length 3
  Top Layer w0.203: C13.2@69.533,86.055 69.533,85.122 69.164,84.753 69.164,83.845 69.43,83.579 U9.9@69.695,83.579
NetC19_1: C19.1 R21.2 R24.1 U11.3 | length 4.3
  Top Layer w0.127: U11.3@70.617,55.348 70.617,56.326 70.146,56.797 R24.1@70.146,57.967 71.465,57.967 C19.1@71.552,57.88
NetC24_1: C24.1 R22.2 R25.1 U12.3 | length 4.5
  Top Layer w0.127: U12.3@70.688,45.443 70.688,46.482 70.178,46.993 R25.1@70.178,48.162 71.433,48.162 C24.1@71.628,47.967
NetC27_2: C27.2 U11.6 | length 1.4
  Top Layer w0.127: C27.2@70.326,51.105 70.326,51.13 70.617,51.421 U11.6@70.617,52.348
NetC28_2: C28.2 U12.6 | length 1.5
  Top Layer w0.127: C28.2@70.351,41.097 70.351,41.122 70.688,41.459 U12.6@70.688,42.443
NetC111_1: C111.1 C112.1 LG1.P1 | length 4.6
  Top Layer w0.254: C112.1@135.839,94.551 135.843,94.554 136.979,94.554 C111.1@136.982,94.557 138.151,95.726 138.151,97.174 LG1.P1@138.395,97.419
NetC117_1: C117.1 U3.43 X1.1 | length 9
  Top Layer w0.203: U3.43@134.076,87.918 137.645,87.918 139.524,89.798 139.524,90.034 139.623,89.935 C117.1@141.987,89.935
NetC118_1: C118.1 U3.42 X1.2 | length 8.6
  Top Layer w0.203: U3.42@134.076,87.518 137.768,87.518 139.173,86.114 139.523,86.114 139.714,86.305 C118.1@142.012,86.305
NetC119_2: C119.2 R28.1 R29.1 U1.E11 | length 8.1
  Top Layer w0.102: R29.1@107.38,68.775 R28.1@109.405,68.775
  Top Layer w0.127: U1.E11@102.21,69.52 v1@102.603,69.914
  Bottom Layer w0.102: v1(102.603,69.918) 102.624,69.918 103.002,69.541 103.535,69.541 103.78,69.296 103.78,68.959 104.036,68.703 104.441,68.703 104.597,68.859 107.112,68.859 v1(107.315,68.656)
NetC122_1: C122.1 U4.26 X3.1 | length 6.9
  Top Layer w0.203: C122.1@131.306,78.207 131.306,76.148 X3.1@130.953,75.795 130.953,75.627 131.702,74.879 132.258,74.879 132.924,74.213 U4.26@132.924,72.603
NetC123_1: C123.1 U4.25 X3.2 | length 6.4
  Top Layer w0.102: C123.1@134.454,78.232 134.454,75.864 X3.2@134.874,75.444
  Top Layer w0.203: U4.25@133.424,72.603 133.424,73.993 X3.2@134.874,75.444
NetC129_1: C129.1 U4.20 | length 1.6
  Top Layer w0.203: U4.20@134.224,69.803 135.791,69.803 C129.1@135.795,69.799
NetC135_1: C135.1 C136.1 R64.1 | length 2.3
  Top Layer w0.254: R64.1@138.735,63.011 138.738,63.014 141.017,63.014 C136.1@141.021,63.017
NetC142_1: C142.1 R73.2 | length 1.1
  Top Layer w0.2: C142.1@84.836,51.791 R73.2@84.836,52.934
NetC145_2: C145.2 R74.1 | length 1.1
  Top Layer w0.305: R74.1@83.954,57.38 C145.2@83.954,58.522
NetC146_2: C146.2 R73.1 U5.G2 U5.G3 | length 14.5
  Top Layer w0.127: U5.G2@91.554,49.734 U5.G3@91.554,50.534
  Top Layer w0.2: R73.1@83.986,52.934 83.972,52.947 C146.2@83.972,54.077 83.972,54.635 84.404,55.067 v1(85.166,55.067)
  Top Layer w0.305: U5.G3@91.554,50.534 v1@91.928,50.161
  Bottom Layer w0.2: v1(85.166,55.067) 85.166,54.559 86.335,53.391 90.297,53.391 91.465,52.222 91.465,50.66 91.948,50.177 v1(91.948,50.14)
NetC148_1: C148.1 C149.1 R23.2 U1.G8 | length 16.7
  Top Layer w0.102: v1(106.697,71.187) 106.77,71.187 106.811,71.145 107.187,71.521 109.682,71.521 110.16,71.044 110.16,69.618 111.227,68.551 111.227,68.174 R23.2@111.227,67.957 ; R23.2@111.252,68.192 111.271,68.174 112.402,68.174 C149.1@112.42,68.192 112.464,68.148 113.545,68.148 C148.1@113.589,68.192
  Top Layer w0.356: U1.G8@100.61,71.92 v1@101.003,72.314
  Bottom Layer w0.102: v1(101.003,72.339) 101.041,72.339 101.473,71.907 101.956,71.907 102.159,71.704 102.684,71.704 102.913,71.476 103.693,71.476 103.794,71.374 105.099,71.374 105.273,71.2 105.499,71.2 105.748,70.95 106.367,70.95 106.608,71.192 106.613,71.187 v1(106.697,71.187)
NetC150_2: C150.2 C152.1 U5.M12 | length 3
  Top Layer w0.152: U5.M12@95.554,57.734 97.213,57.734 ccw(c97.213,57.994) C152.1@97.397,57.81 C150.2@97.397,58.953
NetC151_2: C151.2 R74.2 U5.A11 U5.B11 | length 4.1
  Top Layer w0.127: R74.2@84.804,57.38 84.804,57.355 85.224,56.934 U5.A11@86.754,56.934 U5.B11@87.554,56.934
  Top Layer w0.305: C151.2@84.797,56.21 84.8,56.214 84.8,57.376 R74.2@84.804,57.38
NetC152_2: C152.2 X4.3 | length 2.3
  Top Layer w0.152: C152.2@98.247,57.81 100.053,57.81 cw(c100.053,57.203) X4.3@100.482,57.633
NetCP2_2: CP2.2 RP1.1 RP2.2 UP1.6 | length 4.3
  Top Layer w0.5: CP2.2@107.823,58.076 109.454,58.076 109.479,58.101 UP1.6@109.479,58.141 109.487,58.148 109.487,60.724 RP2.2@109.494,60.731
NetDONE_2: DONE.2 R61.2 | length 1.7
  Top Layer w0.127: DONE.2@86.567,75.921 86.567,74.285 R61.2@86.607,74.244
NetL1_1: L1.1 U6.1 U6.2 U6.3
NetL2_1: L2.1 U7.1 U7.2 U7.3
NetL3_1: L3.1 U8.1 U8.2 U8.3
NetL4_1: L4.1 U9.1 U9.2 U9.3
NetLG1_11: LG1.11 R32.2 | length 19.7
  Top Layer w0.254: LG1.11@139.167,111.268 136.144,108.245 136.144,105.181 140.106,101.219 140.106,94.862 140,94.755 140,94.73 139.827,94.557 R32.2@139.802,94.557
NetLG1_13: LG1.13 R31.2 | length 23.4
  Top Layer w0.254: LG1.13@128.499,111.268 131.404,111.268 134.899,107.772 134.899,105.613 139.598,100.914 139.598,95.523 138.831,94.755 138.831,94.73 138.658,94.557 R31.2@138.633,94.557
NetLP1_1: LP1.1 UP1.3 | length 2.6
  Top Layer w0.5: UP1.3@111.379,55.341 112.655,55.341 113.019,55.704 LP1.1@113.843,55.704
NetP2_2: P2.2 R52.1 R54.1 | length 11.6
  Top Layer w0.3: R54.1@108.883,115.037 108.886,115.033 v1(108.886,114.414) 108.886,113.795 R52.1@108.89,113.792
  Bottom Layer w0.3: v1(108.886,114.414) 113.843,114.414 114.973,113.284 P2.2@118.745,113.284
NetP2_4: P2.4 R48.2 R50.1 | length 27.7
  Top Layer w0.3: R48.2@94.793,112.312 v1(95.428,112.312) 96.062,112.312 96.273,112.522 R50.1@96.273,112.547
  Bottom Layer w0.3: v1(95.428,112.312) 104.463,112.312 105.639,113.487 113.741,113.487 118.745,108.483 P2.4@118.745,108.204
NetQ1_3: Q1.3 R61.1 | length 1.7
  Top Layer w0.127: Q1.3@85.649,72.542 85.757,72.651 R61.1@85.757,74.244
NetQ2_3: Q2.3 R60.1 | length 2.8
  Top Layer w0.102: Q2.3@118.186,70.333 119.844,70.333 120.606,71.095 R60.1@120.606,71.12
NetR2_2: R2.2 U1.H5 | length 1.2
  Top Layer w0.152: U1.H5@99.81,74.32 99.81,74.327 100.203,74.72 v1(100.203,74.727)
  Bottom Layer w0.152: R2.2@99.927,74.178 100.039,74.29 100.039,74.482 100.203,74.646 v1(100.203,74.727)
NetR3_2: R3.2 U1.G5 | length 11.2
  Top Layer w0.152: U1.G5@100.61,74.32 v1(101.016,74.727)
  Bottom Layer w0.102: v1(101.016,74.727) 101.443,74.3 105.589,74.3 105.991,74.701 107.296,74.701 108.032,75.438 109.054,75.438 110.404,76.787 R3.2@110.429,76.787
NetR6_1: R6.1 U2.L8 | length 4.1
  Top Layer w0.152: U2.L8@100.39,95.088 100.315,95.088 100.015,94.788 100.015,93.313 100.49,92.838 v2(100.49,91.988)
  Bottom Layer w0.152: R6.1@99.84,91.938 v2@100.44,91.938
NetR9_2: R9.2 R11.1 U6.5 | length 4.5
  Top Layer w0.203: U6.5@71.882,75.364 71.882,76.094 72.388,76.6 72.388,77.018 R11.1@72.586,77.216 74.918,77.216 R9.2@74.944,77.241
NetR10_2: R10.2 R12.1 U7.5 | length 4.5
  Top Layer w0.203: U7.5@71.857,66.121 71.857,66.867 72.381,67.392 72.381,67.841 R12.1@72.561,68.021 72.586,68.047 R10.2@74.886,68.047
NetR14_2: R14.2 R17.1 U8.5 | length 4.3
  Top Layer w0.203: U8.5@71.968,93.139 71.968,93.869 72.363,94.263 72.363,94.645 R17.1@72.561,94.844 R14.2@74.937,94.844
NetR15_2: R15.2 U9.4 | length 2.9
  Top Layer w0.203: U9.4@72.646,83.579 73.165,83.579 74.498,84.912 74.93,84.912 R15.2@74.955,84.938
NetR16_2: R16.2 R18.1 U9.5 | length 4.4
  Top Layer w0.203: U9.5@71.92,84.305 71.92,85.035 72.363,85.478 72.363,85.882 72.561,86.081 R16.2@74.962,86.081
NetR26_1: R26.1 U3.39 | length 1.8
  Top Layer w0.203: U3.39@134.076,86.318 135.747,86.318 R26.1@135.821,86.393
NetR27_1: R27.1 U3.32 | length 3.5
  Top Layer w0.203: R27.1@130.1,82.068 130.125,82.068 131.776,83.719 U3.32@131.776,84.818
NetR30_2: R30.2 U1.B10 | length 4.2
  Top Layer w0.102: U1.B10@104.61,70.32 104.657,70.368 104.657,70.643 105.054,71.04 105.054,71.247 105.308,71.501 105.884,71.501 106.199,71.186 106.199,70.991 106.421,70.77 107.301,70.77 R30.2@107.55,71.019
NetR37_2: R37.2 X2.3 | length 1.9
  Top Layer w0.127: R37.2@109.511,72.822 111.141,72.822 X2.3@111.303,72.66
NetR38_2: R38.2 U3.20 | length 3.8
  Top Layer w0.203: R38.2@125.572,84.869 125.572,84.894 126.179,85.501 126.179,85.709 126.946,86.476 126.963,86.476 127.602,87.115 128.272,87.115 U3.20@128.276,87.118
NetR42_2: R42.2 U4.1 | length 1.5
  Top Layer w0.203: R42.2@127.654,71.78 127.676,71.803 U4.1@129.124,71.803
NetR44_1: R44.1 U4.24 | length 1.5
  Top Layer w0.203: U4.24@134.224,71.803 135.74,71.803 R44.1@135.763,71.78
NetR55_2: R55.2 U1.R10 | length 6.6
  Top Layer w0.305: v1@93.817,70.714 U1.R10@94.21,70.32
  Bottom Layer w0.102: R55.2@88.233,70.943 88.398,70.943 88.817,70.524 88.926,70.414 92.03,70.414 92.519,70.904 93.341,70.904 93.465,70.78 93.743,70.78 v1(93.81,70.714)
NetR57_2: R57.2 U1.L6 | length 1.3
  Top Layer w0.356: v1@97.017,73.939 U1.L6@97.41,73.546
  Bottom Layer w0.356: R57.2@96.31,74.016 96.369,73.957 96.973,73.957 v1(96.991,73.939)
NetR60_2: R60.2 USR_LED.2 | length 1.6
  Top Layer w0.102: R60.2@121.456,71.12 USR_LED.2@123.038,71.12
NetR62_2: R62.2 USD1.24 | length 1.9
  Top Layer w0.254: USD1.24@124.757,63.497 125.524,63.497 125.864,63.837 R62.2@125.864,64.491
NetR63_2: R63.2 tf1.3 USD1.20 | length 20.3
  Top Layer w0.25: USD1.20@124.757,61.498 126.335,61.498 127.152,60.681 127.152,52.807 128.118,51.841 tf1.3@133.684,51.841 ; tf1.3@133.685,51.841 v1@135.387,51.841
  Bottom Layer w0.25: v1@135.482,51.866 135.507,51.841 136.449,51.841 R63.2@136.474,51.816
  other v1: 135.417,51.865
NetR67_2: R67.2 TU1.1 | length 2.4
  Top Layer w0.254: R67.2@131.928,62.973 131.953,62.973 133.021,61.905 TU1.1@133.873,61.905
NetR68_1: R68.1 TU1.3 | length 2.2
  Top Layer w0.254: TU1.3@135.773,61.905 136.441,61.905 137.541,63.006 R68.1@137.566,63.006
NetR70_1: R70.1 tf1.9 | length 6.8
  Top Layer w0.127: R70.1@126.848,45.212 R70.1@126.898,45.212
  Top Layer w0.25: R70.1@126.898,45.212 126.913,45.227 133.671,45.227 tf1.9@133.685,45.241
NetR72_1: R72.1 USD1.9 | length 1.4
  Top Layer w0.127: R72.1@119.424,62.509 119.434,62.499 USD1.9@120.856,62.499
NetR75_1: R75.1 U5.L4 | length 1.2
  Top Layer w0.127: U5.L4@94.754,51.334 v1(95.154,50.934)
  Bottom Layer w0.127: v1(95.154,50.934) 95.747,50.934 R75.1@95.783,50.971
NetRESET_2: RESET.2 U13.3 | length 3.8
  Top Layer w0.102: U13.3@117.272,74.955 119.596,74.955 120.378,74.173 RESET.2@120.778,74.173
NetRX1_1: RX1.1 T1.3 | length 14.1
  Top Layer w0.483: RX1.1@93.32,26.873 RX1.1@93.32,29.134 93.32,33.314 cw(c95.86,33.314) 94.064,35.11 95.497,36.543 ccw(c93.701,38.339) 96.241,38.339 T1.3@96.241,39.992
NetRX2_1: RX2.1 T2.3 | length 27.8
  Top Layer w0.483: RX2.1@74.422,26.848 RX2.1@74.422,29.134 74.422,34.178 cw(c76.962,34.178) 75.166,35.974 75.177,35.984 cw(c76.973,34.188) 76.973,36.728 89.557,36.728 ccw(c89.557,37.657) 90.213,37 ccw(c88.417,38.797) 90.957,38.797 T2.3@90.957,39.954
NetT3_3: T3.3 TX1.1 | length 37.4
  Top Layer w0.483: T3.3@110.871,45.275 110.871,42.429 ccw(c113.411,42.429) 111.615,40.633 112.565,39.682 ccw(c114.362,41.478) 114.362,38.938 129.732,38.938 cw(c129.732,36.398) 131.529,38.194 132.035,37.688 cw(c130.238,35.892) 132.779,35.892 TX1.1@132.779,29.058 TX1.1@132.779,26.721
NetT4_3: T4.3 TX2.1 | length 21.6
  Top Layer w0.483: T4.3@105.131,42.684 105.131,40.448 ccw(c107.671,40.448) 105.875,38.651 107.104,37.422 ccw(c108.901,39.218) 108.901,36.678 111.216,36.678 cw(c111.216,34.138) 113.012,35.934 113.15,35.796 cw(c111.354,34) 113.894,34 TX2.1@113.894,29.134 TX2.1@113.894,26.873
Nettf1_1: tf1.1 USD1.23 | length 15.8
  Top Layer w0.254: USD1.23@124.757,63 127.399,63 128.355,62.043 128.355,56.684 130.998,54.041 tf1.1@133.685,54.041
Nettf1_2: tf1.2 USD1.22 | length 17.7
  Top Layer w0.254: USD1.22@124.757,62.499 126.858,62.499 127.635,61.722 127.635,53.518 128.203,52.95 133.676,52.95 tf1.2@133.685,52.941
Nettf1_5: tf1.5 USD1.19 | length 19.4
  Top Layer w0.25: USD1.19@124.757,60.998 125.997,60.998 126.771,60.223 126.771,50.343 127.473,49.641 tf1.5@133.685,49.641
Nettf1_7: tf1.7 USD1.18 | length 20.3
  Top Layer w0.25: USD1.18@124.056,60.3 124.056,59.332 126.263,57.125 126.263,48.957 127.779,47.441 tf1.7@133.684,47.441
Nettf1_8: tf1.8 USD1.16 | length 22.4
  Top Layer w0.25: USD1.16@123.055,60.3 123.055,56.929 125.349,54.635 125.349,47.803 126.81,46.341 129.235,46.341 ; 129.236,46.341 tf1.8@133.685,46.341
OTG_CLK: R42.1 U1.A11 | length 25.6
  Top Layer w0.102: U1.A11@105.41,69.52 106.121,69.52 106.324,69.317 106.324,68.402 107.111,67.615 109.288,67.615 110.453,66.45 114.112,66.45 116.674,69.012 120.244,69.012 121.336,70.104 v1(121.387,70.104) ; v1(126.213,70.79) 126.213,71.171 R42.1@126.619,71.577
  Bottom Layer w0.102: v1(121.387,70.104) 121.412,70.104 122.428,71.12 125.882,71.12 v1(126.213,70.79)
OTG_DATA0: U1.A14 U4.3 | length 27.4
  Top Layer w0.102: U1.A14@105.41,67.12 105.477,67.12 105.668,66.929 106.268,66.929 106.437,66.761 108.993,66.761 110.116,65.638 114.449,65.638 116.756,67.945 119.896,67.945 120.048,67.793 120.286,67.793 120.32,67.759 v1@120.32,67.716 ; v1@126.035,68.199 126.39,68.199 126.949,68.758 126.949,69.063 127.787,69.901 127.787,70.561 128.029,70.803 U4.3@129.124,70.803
  Bottom Layer w0.102: v1(120.447,67.716) 121.158,67.716 121.945,68.504 125.699,68.504 v1(126.015,68.188)
OTG_DATA1: U1.D15 U4.4 | length 32.9
  Top Layer w0.102: v1(128.27,70.307) 128.272,70.305 129.122,70.305 U4.4@129.124,70.303
  Top Layer w0.127: U1.D15@103.01,66.32 103.414,65.917 v1(103.418,65.917)
  Bottom Layer w0.102: v1(103.418,65.917) 103.803,66.301 108.187,66.301 108.829,65.659 117.199,65.659 118.233,66.694 118.233,70.445 120.179,72.39 126.729,72.39 128.016,71.103 128.016,70.637 v1@128.321,70.333
OTG_DATA2: U1.A12 U4.5 | length 27.5
  Top Layer w0.102: U1.A12@105.41,68.72 105.429,68.702 105.737,68.702 107.068,67.37 109.245,67.37 110.368,66.247 114.196,66.247 116.707,68.758 120.859,68.758 v1(121.05,68.949) ; v1(126.975,68.174) 127.152,68.351 127.152,68.936 128.02,69.803 U4.5@129.124,69.803
  Bottom Layer w0.102: v1(121.05,68.949) 121.12,68.949 121.12,69.02 121.392,69.291 122.199,69.291 122.555,68.936 126.136,68.936 126.898,68.174 v1(126.975,68.174)
OTG_DATA3: U1.F12 U4.6 | length 39.6
  Top Layer w0.102: v1@122.758,65.837 123.749,66.827 126.34,66.827 127.381,67.869 127.381,68.877 127.807,69.303 U4.6@129.124,69.303
  Top Layer w0.127: U1.F12@101.41,68.72 v1@101.803,69.114
  Bottom Layer w0.102: v1(101.803,69.118) 101.051,68.367 101.051,68.084 100.609,67.642 100.609,66.715 100.777,66.548 100.777,65.528 103.033,63.271 104.877,63.271 105.461,62.687 105.521,62.687 105.868,62.34 106.595,62.34 106.947,61.989 117.157,61.989 117.856,61.29 119.565,61.29 120.599,62.324 120.599,63.678 v1(122.784,65.862)
OTG_DATA4: U1.C16 U4.7 | length 32.4
  Top Layer w0.102: v1(127.894,68.803) U4.7@129.124,68.803
  Top Layer w0.127: U1.C16@103.81,65.52 v1@104.203,65.127
  Bottom Layer w0.102: v1@104.234,65.1 108.526,65.1 108.577,65.049 117.451,65.049 118.843,66.441 118.843,70.186 120.437,71.78 126.111,71.78 126.924,70.968 126.924,69.774 v1(127.894,68.803)
  Bottom Layer w0.127: v1(104.208,65.127) v1@104.234,65.1
OTG_DATA5: U1.A10 U4.9 | length 31.5
  Top Layer w0.102: U1.A10@105.41,70.32 105.803,70.32 106.528,69.596 106.528,68.486 107.195,67.818 109.372,67.818 110.537,66.654 114.028,66.654 116.666,69.291 119.71,69.291 v1(119.939,69.52) ; v1(125.298,67.92) v1(125.298,69.367) ; v1(129.845,66.37) 129.889,66.415 129.889,67.469 U4.9@129.924,67.503
  Bottom Layer w0.102: v1(119.939,69.52) 120.599,69.52 120.752,69.672 122.199,69.672 122.733,69.139 125.07,69.139 v1(125.298,69.367) ; v1(125.298,67.92) 125.882,67.335 128.88,67.335 129.769,66.446 129.845,66.446 v1(129.845,66.37)
OTG_DATA6: U1.E13 U4.10 | length 32.4
  Top Layer w0.102: v1(116.662,66.98) 116.7,66.942 117.04,66.942 117.281,66.7 117.627,66.7 117.754,66.827 117.756,66.827 117.832,66.904 121.133,66.904 v1(122.209,67.98) ; v1@130.423,66.638 U4.10@130.424,67.503
  Top Layer w0.127: U1.E13@102.21,67.92 v1@102.603,67.527
  Bottom Layer w0.102: v1(102.608,67.527) 102.608,67.589 103.116,68.097 103.836,68.097 103.956,68.217 104.681,68.217 105.581,67.317 108.608,67.317 109.224,66.7 116.383,66.7 v1(116.662,66.98) ; v1(122.209,67.98) 122.276,68.047 122.342,67.98 124.704,67.98 126.771,65.913 130.073,65.913 130.404,66.243 v1@130.404,66.7
  other v1: 130.422,66.637
OTG_DATA7: U1.C18 U4.13 | length 31.9
  Top Layer w0.102: U1.C18@103.81,63.92 104.147,63.92 104.542,63.525 116.178,63.525 118.159,65.507 119.707,65.507 v1(119.71,65.51) ; U4.13@131.924,67.503 131.955,67.471 131.955,66.709 v1(131.987,66.677)
  Bottom Layer w0.102: v1(119.71,65.51) 120.9,66.7 125.654,66.7 126.844,65.51 131.499,65.51 131.953,65.964 v1@131.953,66.675
OTG_DIR: U1.C13 U4.31 | length 32.3
  Top Layer w0.102: v1(117.45,67.208) 118.974,67.208 119.076,67.107 120.726,67.107 v1(123.19,69.571) ; v1(125.679,70.536) 125.679,71.501 127.975,73.797 130.071,73.797 130.424,73.444 U4.31@130.424,72.603
  Top Layer w0.127: U1.C13@103.81,67.92 103.861,67.92 104.145,67.637 v1(104.196,67.637)
  Bottom Layer w0.102: v1(104.196,67.637) 104.686,67.637 105.412,66.911 108.439,66.911 109.082,66.269 116.946,66.269 117.45,66.772 117.45,67.142 v1@117.516,67.208 ; v1(123.19,69.571) 123.774,70.155 125.298,70.155 v1(125.679,70.536)
OTG_NXT: U1.E16 U4.2 | length 33.1
  Top Layer w0.102: v1@127.381,70.714 127.971,71.303 U4.2@129.124,71.303
  Top Layer w0.127: U1.E16@102.21,65.52 102.216,65.52 102.605,65.131 v1(102.611,65.131)
  Bottom Layer w0.102: v1(102.611,65.131) 102.653,65.131 103.027,65.504 104.364,65.504 104.565,65.303 108.61,65.303 108.661,65.253 117.367,65.253 118.64,66.525 118.64,70.27 120.353,71.984 126.195,71.984 127.356,70.823 v1(127.356,70.739)
OTG_RESETN: C121.2 R33.1 U1.D16 U4.27 | length 46
  Top Layer w0.127: U1.D16@103.01,65.52 v1@103.403,65.127
  Top Layer w0.152: v1(126.619,69.367) 125.933,69.367 125.07,70.231 125.07,71.628 128.041,74.6 R33.1@128.041,75.387 128.048,75.394 C121.2@129.21,75.394 129.21,74.625 129.515,74.32 131.953,74.32 132.424,73.85 U4.27@132.424,72.603
  Bottom Layer w0.102: v1(103.407,65.127) 103.815,64.719 108.365,64.719 108.492,64.846 117.535,64.846 119.046,66.357 119.046,70.102 120.522,71.577 126.027,71.577 126.644,70.96 v1@126.644,69.19
OTG_STP: U1.C15 U4.29 | length 42.7
  Top Layer w0.102: v1(127.381,70.028) 125.603,70.028 125.298,70.333 125.298,71.476 127.914,74.092 131.216,74.092 131.424,73.885 U4.29@131.424,72.603
  Top Layer w0.127: U1.C15@103.81,66.32 v1@104.206,65.924
  Bottom Layer w0.102: v1(104.208,65.924) 104.232,65.924 104.649,65.507 108.694,65.507 108.745,65.456 117.283,65.456 118.437,66.61 118.437,70.354 120.269,72.187 126.442,72.187 127.733,70.895 127.733,70.38 v1(127.381,70.028)
PG_1V0: R7.2 U6.4 U7.13 | length 20.5
  Top Layer w0.203: U6.4@72.608,74.638 73.165,74.638 74.456,75.929 74.768,75.929 R7.2@74.937,76.098
  Top Layer w0.25: v1(70.206,62.357) 70.358,62.509 U7.13@70.358,63.17
  Bottom Layer w0.25: v1(70.206,62.357) 72.314,62.357 74.778,64.821 74.778,74.905 v1(74.092,75.59)
PG_1V5: R13.2 U8.4 U9.13 | length 20
  Top Layer w0.203: U8.4@72.695,92.413 72.709,92.427 73.149,92.427 74.346,93.624 74.886,93.624 R13.2@74.937,93.675
  Top Layer w0.25: v1(70.155,80.391) 70.421,80.658 U9.13@70.421,81.354
  Bottom Layer w0.25: v1(70.155,80.391) 70.155,92.405 71.018,93.269 v1(73.965,93.269)
PG_1V8: R8.2 U7.4 U8.13 | length 30.2
  Top Layer w0.203: U7.4@72.583,65.395 73.167,65.395 74.456,66.684 74.688,66.684 74.886,66.882 R8.2@74.886,66.904
  Top Layer w0.25: U8.13@70.47,90.188 70.47,88.128 v1@70.917,87.681
  Bottom Layer w0.25: v1(70.907,87.677) 74.574,84.009 74.574,77.749 73.558,76.733 73.558,73.914 74.426,73.046 74.426,66.73 v1(73.482,65.786)
PHY_AD0/LED0: R31.1 R46.2 U3.35 | length 24.7
  Top Layer w0.203: U3.35@132.976,84.818 132.976,83.542 133.579,82.939 133.579,82.094 R46.2@133.554,82.068
  Top Layer w0.254: v1@138.633,92.583 R31.1@138.633,93.707
  Bottom Layer w0.254: v1(133.521,82.934) 133.574,82.934 133.958,82.55 139.979,82.55 142.697,85.268 142.697,90.429 141.178,91.948 139.239,91.948 v1(138.626,92.561)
